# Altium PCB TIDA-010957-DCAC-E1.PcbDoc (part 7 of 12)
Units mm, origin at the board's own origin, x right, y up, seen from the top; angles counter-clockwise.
Board outline 300 x 300 mm, 4 copper layers (Top Layer, Layer 1, Layer 2, Bottom Layer), stack 1.787 mm thick; 1159 components, 619 nets, 3431 pads, 2942 vias.
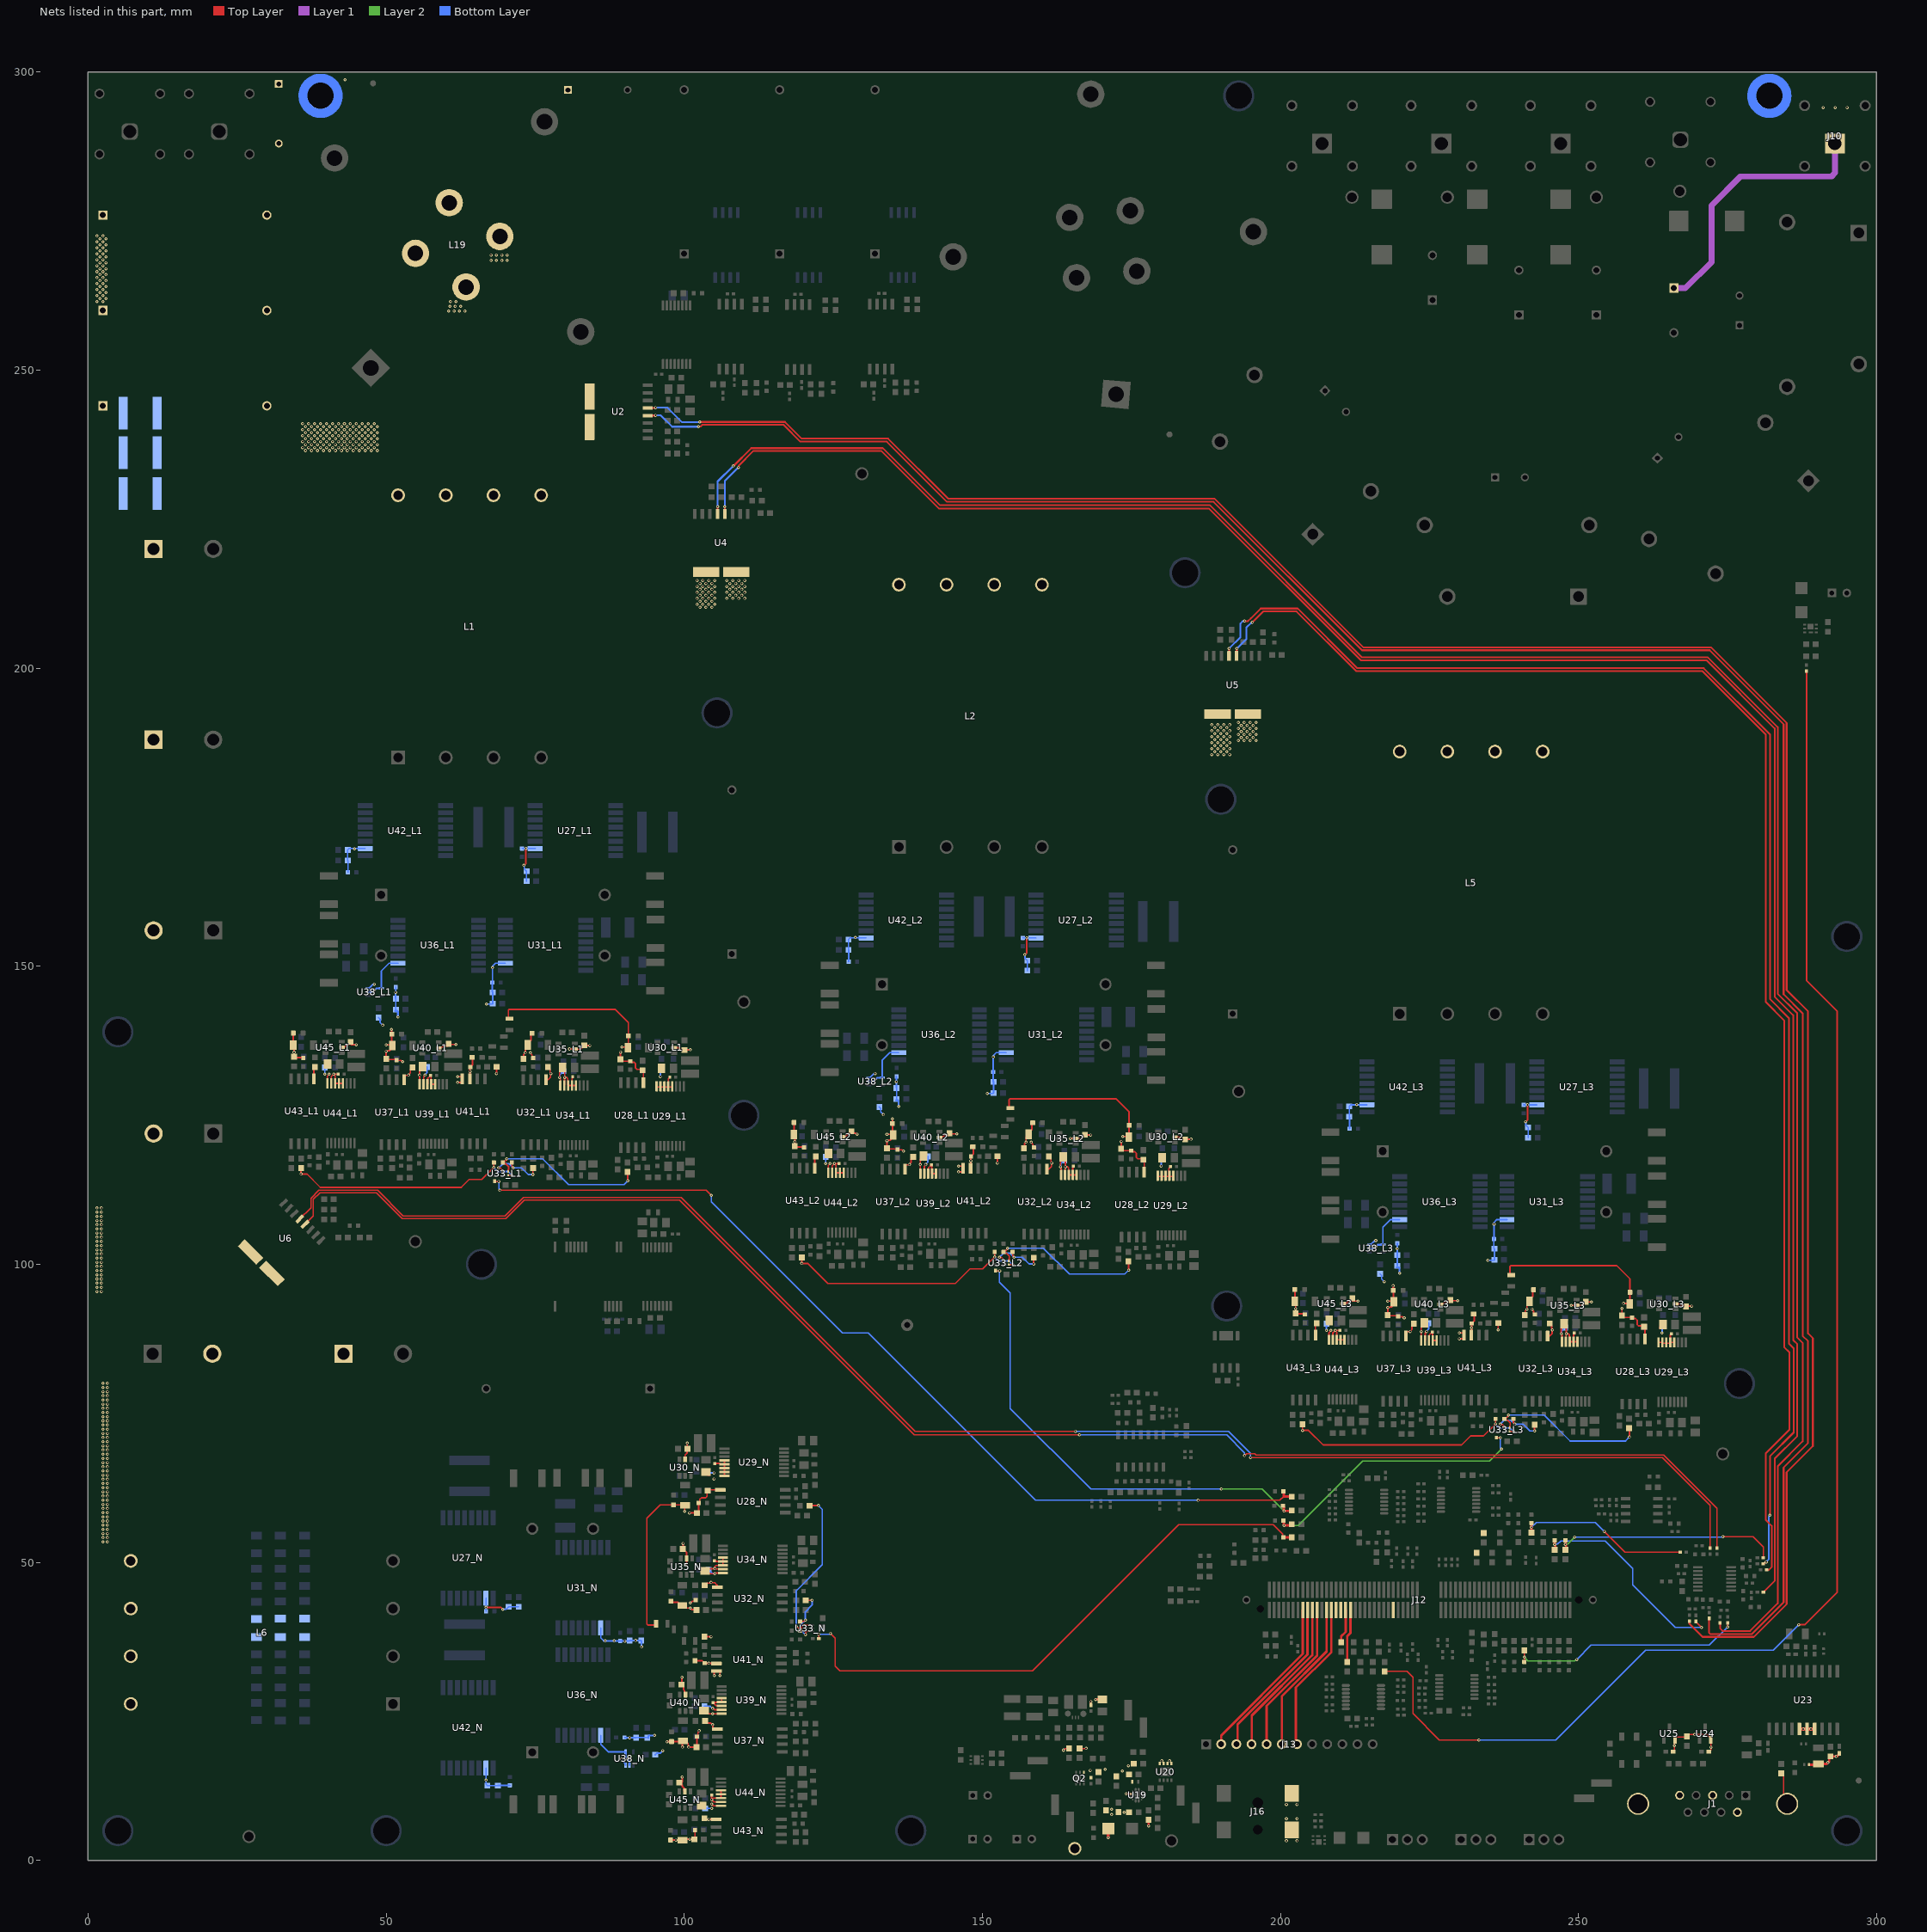
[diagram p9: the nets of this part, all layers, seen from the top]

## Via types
v1: diameter 0.508, hole 0.254, Top Layer to Bottom Layer, tented both sides, 2942 vias

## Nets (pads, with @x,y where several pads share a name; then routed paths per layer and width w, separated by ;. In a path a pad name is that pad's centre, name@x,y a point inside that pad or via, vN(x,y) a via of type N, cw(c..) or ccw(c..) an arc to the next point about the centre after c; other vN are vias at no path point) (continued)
GND_ISO_CAN: C149.2 C150.2 C151.2 C156.2 C157.1 C158.1 FB18.2 J1.3 J1.5 J1.6 J1.10 J1.11 R93.1 U23.15 U23.16 U23.17 U24.2 U25.2 | length 25.8
  Top Layer w0.2: C156.2@265.85,18.25 265.873,18.25 266.073,18.45 v1(266.073,19.262) 266.073,20.073 U25.2@266.2,20.2 266.2,20.479 266.4,20.679 268.079,20.679 C157.1@268.2,20.8 268.55,21.15 271.6,21.15 272.2,20.55 U24.2@272.2,20.2 272.2,18.5 271.95,18.25 C158.1@271.85,18.25 ; R93.1@284,14.6 284.375,14.225 284.375,10.125 J1.10@285,9.5 ; C151.2@290.1,16.05 C151.2@290.25,16.2 ; C149.2@293.75,17.85 C149.2@293.75,17.95
  Top Layer w0.4: FB18.2@288.65,16.05 C151.2@290.1,16.05 ; C151.2@290.25,16.2 291.634,16.2 292.055,16.621 292.055,17.255 C150.2@292.25,17.45 293.35,17.45 C149.2@293.75,17.85
  Top Layer w0.55: U23.15@287.06,22.05 U23.16@288.33,22.05 U23.17@289.6,22.05
  other v1: 291.845,16.411 293.229,17.45 272.2,19 269.5,21.1 287.695,22.05 288.965,22.05
GND_S1_GaN_L1: C187_L1.2 C188_L1.1 C189_L1.1 C190_L1.2 C192_L1.2 C193_L1.1 C194_L1.2 C195_L1.2 D10_L1.1 R283_L1.1 R288_L1.1 R290_L1.1 R314_L1.2 U27_L1.10 U28_L1.5 U29_L1.12 U29_L1.13 U29_L1.14 U29_L1.15 U29_L1.16 U30_L1.2 | length 52.9
  Top Layer w0.254: R314_L1.2@70.5,141.2 70.5,142.621 70.649,142.77 88.4,142.77 90.625,140.545 D10_L1.1@90.625,138.303 90.625,136.395 C192_L1.2@90.575,136.345 90.48,136.44 v1(89.55,136.44) ; v1(73.119,166.926) 73.173,166.926 73.449,167.201 v1(73.449,169.748) ; v1(89.3,135.603) C187_L1.2@89.3,134.394 89.627,134.066 C189_L1.1@90.967,134.066 91.135,133.898 91.55,133.898 91.838,133.61 91.838,132.907 92.062,132.684 92.865,132.684 C195_L1.2@93,132.548 93.155,132.393 U28_L1.5@93.155,130.45 ; U29_L1.16@95.497,129.75 96.025,129.75 96.675,129.75 97.272,129.75 U29_L1.12@97.922,129.75 ; C194_L1.2@95.664,132.196 C194_L1.2@95.664,132.569 ; U29_L1.13@97.325,129.855 97.325,131.104 C193_L1.1@97.588,131.367 ; U30_L1.2@98.288,136.345 99.013,136.345 99.322,136.036 99.322,136.014 99.973,136.014 R290_L1.1@100.047,135.94 100.096,135.989 v1(101,135.989)
  Bottom Layer w0.254: C188_L1.1@72.801,169.747 72.803,169.748 v1(73.449,169.748) 74.998,169.748 U27_L1.10@75,169.75 ; v1(73.119,166.926) 73.168,166.877 73.168,166.34 73.178,166.33 73.178,166.305 73.526,165.957 C190_L1.2@73.551,165.957 R283_L1.1@73.551,164.25
  Bottom Layer w0.3: v1(96,131.5) 96,132.7 R288_L1.1@96.2,132.9
GND_S1_GaN_L2: C187_L2.2 C188_L2.1 C189_L2.1 C190_L2.2 C192_L2.2 C193_L2.1 C194_L2.2 C195_L2.2 D10_L2.1 R283_L2.1 R288_L2.1 R290_L2.1 R314_L2.2 U27_L2.10 U28_L2.5 U29_L2.12 U29_L2.13 U29_L2.14 U29_L2.15 U29_L2.16 U30_L2.2 | length 53.1
  Top Layer w0.254: R314_L2.2@154.5,126.2 154.5,127.621 154.649,127.77 172.4,127.77 174.625,125.545 D10_L2.1@174.625,123.303 174.625,121.395 C192_L2.2@174.575,121.345 174.48,121.44 v1(173.55,121.44) ; v1(157.119,151.926) 157.173,151.926 157.449,152.201 v1(157.449,154.748) ; v1(173.3,120.603) C187_L2.2@173.3,119.394 173.627,119.066 C189_L2.1@174.967,119.066 175.135,118.898 175.55,118.898 175.838,118.61 175.838,117.907 176.062,117.684 176.865,117.684 C195_L2.2@177,117.548 177.155,117.393 U28_L2.5@177.155,115.45 ; U29_L2.16@179.497,114.75 179.972,114.75 180.622,114.75 U29_L2.13@181.272,114.75 ; C194_L2.2@179.664,117.196 C194_L2.2@179.664,117.569 ; C193_L2.1@181.588,116.367 181.272,116.051 U29_L2.13@181.272,114.75 ; U29_L2.12@181.922,114.75 U29_L2.13@181.272,114.75 ; U30_L2.2@182.288,121.345 183.013,121.345 183.322,121.036 183.322,121.014 183.973,121.014 R290_L2.1@184.047,120.94 184.096,120.989 v1(185,120.989)
  Bottom Layer w0.254: C188_L2.1@156.801,154.747 156.803,154.748 v1(157.449,154.748) 158.998,154.748 U27_L2.10@159,154.75 ; v1(157.119,151.926) 157.168,151.877 157.168,151.34 157.178,151.33 157.178,151.305 157.526,150.957 C190_L2.2@157.551,150.957 R283_L2.1@157.551,149.25
  Bottom Layer w0.3: v1(180,116.5) 180,117.7 R288_L2.1@180.2,117.9
GND_S1_GaN_L3: C187_L3.2 C188_L3.1 C189_L3.1 C190_L3.2 C192_L3.2 C193_L3.1 C194_L3.2 C195_L3.2 D10_L3.1 R283_L3.1 R288_L3.1 R290_L3.1 R314_L3.2 U27_L3.10 U28_L3.5 U29_L3.12 U29_L3.13 U29_L3.14 U29_L3.15 U29_L3.16 U30_L3.2 | length 53.1
  Top Layer w0.254: R314_L3.2@238.5,98.2 238.5,99.621 238.649,99.77 256.4,99.77 258.625,97.545 D10_L3.1@258.625,95.303 258.625,93.395 C192_L3.2@258.575,93.345 258.48,93.44 v1(257.55,93.44) ; v1(241.119,123.926) 241.173,123.926 241.449,124.201 v1(241.449,126.748) ; v1(257.3,92.603) C187_L3.2@257.3,91.394 257.627,91.066 C189_L3.1@258.967,91.066 259.135,90.898 259.55,90.898 259.838,90.61 259.838,89.907 260.062,89.684 260.865,89.684 C195_L3.2@261,89.548 261.155,89.393 U28_L3.5@261.155,87.45 ; U29_L3.16@263.425,86.9 U29_L3.15@264.075,86.9 ; C194_L3.2@263.664,89.196 C194_L3.2@263.664,89.569 ; U29_L3.15@264.147,86.75 264.725,86.75 265.272,86.75 265.297,86.75 265.4,86.853 265.4,88.179 C193_L3.1@265.588,88.367 ; U29_L3.13@265.375,86.9 U29_L3.12@266.025,86.9 ; U30_L3.2@266.288,93.345 267.013,93.345 267.322,93.036 267.322,93.014 267.973,93.014 R290_L3.1@268.047,92.94 268.096,92.989 v1(269,92.989)
  Bottom Layer w0.254: C188_L3.1@240.801,126.747 240.803,126.748 v1(241.449,126.748) 242.998,126.748 U27_L3.10@243,126.75 ; v1(241.119,123.926) 241.168,123.877 241.168,123.34 241.178,123.33 241.178,123.305 241.526,122.957 C190_L3.2@241.551,122.957 R283_L3.1@241.551,121.25
  Bottom Layer w0.3: v1(264,88.5) 264,89.7 R288_L3.1@264.2,89.9
GND_S1_GaN_N: C187_N.2 C188_N.1 C189_N.1 C190_N.2 C192_N.2 C193_N.1 C194_N.2 C195_N.2 D10_N.1 R283_N.1 R288_N.1 R290_N.1 R314_N.2 U27_N.10 U28_N.5 U29_N.12 U29_N.13 U29_N.14 U29_N.15 U29_N.16 U30_N.2 | length 53.2
  Top Layer w0.254: v1(66.752,42.449) 69.299,42.449 69.574,42.173 v1(69.574,42.119) ; R314_N.2@95.3,39.5 93.879,39.5 93.73,39.649 93.73,57.4 95.955,59.625 D10_N.1@98.197,59.625 100.105,59.625 C192_N.2@100.155,59.575 100.06,59.48 v1(100.06,58.55) ; U30_N.2@100.155,67.288 100.155,68.013 100.464,68.322 100.486,68.322 100.486,68.973 R290_N.1@100.56,69.047 100.511,69.096 v1(100.511,70) ; v1(100.897,58.3) C187_N.2@102.106,58.3 102.434,58.627 C189_N.1@102.434,59.967 102.602,60.135 102.602,60.55 102.89,60.838 103.593,60.838 103.816,61.062 103.816,61.865 C195_N.2@103.952,62 104.107,62.155 U28_N.5@106.05,62.155 ; C194_N.2@103.931,64.664 C194_N.2@104.304,64.664 ; C193_N.1@105.133,66.588 105.964,66.588 106.105,66.447 U29_N.13@106.75,66.447 ; U29_N.16@106.75,64.497 U29_N.15@106.75,65.147 U29_N.14@106.75,65.797 U29_N.13@106.75,66.447 ; U29_N.12@106.75,67.097 U29_N.13@106.75,66.447
  Bottom Layer w0.254: U27_N.10@66.75,44 66.752,43.998 v1(66.752,42.449) 66.752,41.803 C188_N.1@66.753,41.801 ; v1(69.574,42.119) 69.623,42.168 70.16,42.168 70.17,42.178 70.195,42.178 70.543,42.526 C190_N.2@70.543,42.551 R283_N.1@72.25,42.551
  Bottom Layer w0.3: R288_N.1@103.6,65.2 103.8,65 v1(105,65)
  other v1: 105,64
GND_S2_GaN_L1: C201_L1.2 C202_L1.1 C203_L1.1 C204_L1.2 C208_L1.2 C210_L1.1 C211_L1.2 C212_L1.2 D11_L1.1 R294_L1.1 R299_L1.1 R301_L1.1 U31_L1.10 U32_L1.5 U34_L1.12 U34_L1.13 U34_L1.14 U34_L1.15 U34_L1.16 U35_L1.2 | length 33.6
  Top Layer w0.254: C201_L1.2@73.005,134.466 73.07,134.531 73.07,135.199 v1(73.347,135.476) 73.347,136.393 C208_L1.2@73.755,136.8 ; v1(74.185,135.476) 74.185,135.407 74.484,135.108 74.484,134.758 C203_L1.1@74.66,134.582 ; U32_L1.5@76.815,130.95 76.853,130.988 77.174,130.988 77.581,131.396 77.581,131.95 v1(77.63,131.998) 77.63,132.067 77.503,132.194 C212_L1.2@77.503,132.723 ; U34_L1.16@79.225,130 79.225,131.155 79.1,131.28 v1(79.1,131.349) 79.1,132.239 79.584,132.723 79.95,132.357 v1(79.95,131.349) ; U34_L1.15@79.875,130 79.913,130.038 79.913,131.312 v1(79.95,131.349) ; v1(80.775,136.116) U35_L1.2@81.65,136.116 81.681,136.085 82.62,136.085 83.244,136.709 R301_L1.1@83.244,136.734 83.288,136.69 v1(84.173,136.69) ; C210_L1.1@81.394,131.367 81.175,131.148 U34_L1.13@81.175,130 ; U34_L1.12@81.825,130 U34_L1.13@81.175,130 ; v1(79.95,131.349) 80.284,131.349 80.461,131.172 80.461,130.064 U34_L1.14@80.525,130 U34_L1.13@81.175,130
  Top Layer w0.3: C208_L1.2@73.755,136.8 73.755,137.05 74.3,137.595 D11_L1.1@74.3,138.8
  Bottom Layer w0.254: v1(66.819,143.657) 67.823,143.657 R294_L1.1@67.89,143.725 67.89,145.617 C204_L1.2@67.882,145.625 67.807,145.7 C202_L1.1@67.807,147.25 67.833,147.276 67.833,150.007 68.326,150.5 U31_L1.10@70,150.5 ; v1(79.1,131.349) 79.149,131.398 79.149,131.795 79.736,132.382 R299_L1.1@79.736,132.407
  other v1: 67.833,149.758
GND_S2_GaN_L2: C201_L2.2 C202_L2.1 C203_L2.1 C204_L2.2 C208_L2.2 C210_L2.1 C211_L2.2 C212_L2.2 D11_L2.1 R294_L2.1 R299_L2.1 R301_L2.1 U31_L2.10 U32_L2.5 U34_L2.12 U34_L2.13 U34_L2.14 U34_L2.15 U34_L2.16 U35_L2.2 | length 33.6
  Top Layer w0.254: C201_L2.2@157.005,119.466 157.07,119.531 157.07,120.199 v1(157.347,120.476) 157.347,121.393 C208_L2.2@157.755,121.8 ; v1(158.185,120.476) 158.185,120.407 158.484,120.108 158.484,119.758 C203_L2.1@158.66,119.582 ; U32_L2.5@160.815,115.95 160.853,115.988 161.174,115.988 161.581,116.396 161.581,116.95 v1(161.63,116.998) 161.63,117.067 161.503,117.194 C212_L2.2@161.503,117.723 ; U34_L2.16@163.225,115 163.225,116.155 163.1,116.28 v1(163.1,116.349) 163.1,117.239 163.584,117.723 163.95,117.357 v1(163.95,116.349) ; U34_L2.15@163.875,115 163.913,115.038 163.913,116.312 v1(163.95,116.349) ; v1(164.775,121.116) U35_L2.2@165.65,121.116 165.681,121.085 166.62,121.085 167.244,121.709 R301_L2.1@167.244,121.734 167.288,121.69 v1(168.173,121.69) ; C210_L2.1@165.394,116.367 165.175,116.148 U34_L2.13@165.175,115 ; U34_L2.12@165.825,115 U34_L2.13@165.175,115 ; v1(163.95,116.349) 164.284,116.349 164.461,116.172 164.461,115.064 U34_L2.14@164.525,115 U34_L2.13@165.175,115
  Top Layer w0.3: C208_L2.2@157.755,121.8 157.755,122.05 158.3,122.595 D11_L2.1@158.3,123.8
  Bottom Layer w0.254: v1(150.819,128.657) 151.823,128.657 R294_L2.1@151.89,128.725 151.89,130.617 C204_L2.2@151.882,130.625 151.807,130.7 C202_L2.1@151.807,132.25 151.833,132.276 151.833,135.007 152.326,135.5 U31_L2.10@154,135.5 ; v1(163.1,116.349) 163.149,116.398 163.149,116.795 163.736,117.382 R299_L2.1@163.736,117.407
  other v1: 151.833,134.758
GND_S2_GaN_L3: C201_L3.2 C202_L3.1 C203_L3.1 C204_L3.2 C208_L3.2 C210_L3.1 C211_L3.2 C212_L3.2 D11_L3.1 R294_L3.1 R299_L3.1 R301_L3.1 U31_L3.10 U32_L3.5 U34_L3.12 U34_L3.13 U34_L3.14 U34_L3.15 U34_L3.16 U35_L3.2 | length 33.6
  Top Layer w0.254: C201_L3.2@241.005,91.466 241.07,91.531 241.07,92.199 v1(241.347,92.476) 241.347,93.393 C208_L3.2@241.755,93.8 ; v1(242.185,92.476) 242.185,92.407 242.484,92.108 242.484,91.758 C203_L3.1@242.66,91.582 ; U32_L3.5@244.815,87.95 244.853,87.988 245.174,87.988 245.581,88.396 245.581,88.95 v1(245.63,88.998) 245.63,89.067 245.503,89.194 C212_L3.2@245.503,89.723 ; U34_L3.16@247.225,87 247.225,88.155 247.1,88.28 v1(247.1,88.349) 247.1,89.239 247.584,89.723 247.95,89.357 v1(247.95,88.349) ; U34_L3.15@247.875,87 247.913,87.038 247.913,88.312 v1(247.95,88.349) ; v1(248.775,93.116) U35_L3.2@249.65,93.116 249.681,93.085 250.62,93.085 251.244,93.709 R301_L3.1@251.244,93.734 251.288,93.69 v1(252.173,93.69) ; C210_L3.1@249.394,88.367 249.175,88.148 U34_L3.13@249.175,87 ; U34_L3.12@249.825,87 U34_L3.13@249.175,87 ; v1(247.95,88.349) 248.284,88.349 248.461,88.172 248.461,87.064 U34_L3.14@248.525,87 U34_L3.13@249.175,87
  Top Layer w0.3: C208_L3.2@241.755,93.8 241.755,94.05 242.3,94.595 D11_L3.1@242.3,95.8
  Bottom Layer w0.254: v1(234.819,100.657) 235.823,100.657 R294_L3.1@235.89,100.725 235.89,102.617 C204_L3.2@235.882,102.625 235.807,102.7 C202_L3.1@235.807,104.25 235.833,104.276 235.833,107.007 236.326,107.5 U31_L3.10@238,107.5 ; v1(247.1,88.349) 247.149,88.398 247.149,88.795 247.736,89.382 R299_L3.1@247.736,89.407
  other v1: 235.833,106.758
GND_S2_GaN_N: C201_N.2 C202_N.1 C203_N.1 C204_N.2 C208_N.2 C210_N.1 C211_N.2 C212_N.2 D11_N.1 R294_N.1 R299_N.1 R301_N.1 U31_N.10 U32_N.5 U34_N.12 U34_N.13 U34_N.14 U34_N.15 U34_N.16 U35_N.2 | length 33.6
  Top Layer w0.254: C208_N.2@99.7,42.755 100.107,42.347 v1(101.024,42.347) 101.301,42.07 101.969,42.07 C201_N.2@102.034,42.005 ; v1(99.81,53.173) 99.81,52.288 R301_N.1@99.766,52.244 99.791,52.244 100.415,51.62 100.415,50.681 U35_N.2@100.384,50.65 v1(100.384,49.775) ; v1(101.024,43.185) 101.093,43.185 101.392,43.484 101.742,43.484 C203_N.1@101.918,43.66 ; C212_N.2@103.777,46.503 104.306,46.503 104.433,46.63 v1(104.502,46.63) 104.55,46.581 105.104,46.581 105.512,46.174 105.512,45.853 U32_N.5@105.55,45.815 ; C210_N.1@105.133,50.394 105.352,50.175 U34_N.13@106.5,50.175 ; U34_N.16@106.5,48.225 105.345,48.225 105.22,48.1 v1(105.151,48.1) 104.261,48.1 103.777,48.584 104.143,48.95 v1(105.151,48.95) ; U34_N.15@106.5,48.875 106.462,48.913 105.188,48.913 v1(105.151,48.95) ; U34_N.12@106.5,50.825 U34_N.13@106.5,50.175 ; v1(105.151,48.95) 105.151,49.284 105.328,49.461 106.436,49.461 U34_N.14@106.5,49.525 U34_N.13@106.5,50.175
  Top Layer w0.3: D11_N.1@97.7,43.3 98.905,43.3 99.45,42.755 C208_N.2@99.7,42.755
  Bottom Layer w0.254: U31_N.10@86,39 86,37.326 86.493,36.833 89.224,36.833 C202_N.1@89.25,36.807 90.8,36.807 C204_N.2@90.875,36.882 90.883,36.89 R294_N.1@92.775,36.89 92.843,36.823 v1(92.843,35.819) ; R299_N.1@104.093,48.736 104.118,48.736 104.705,48.149 105.102,48.149 v1(105.151,48.1)
  other v1: 90.025,36.807 86.742,36.833 88.242,36.833 91.829,36.89
GND_S3_GaN_L1: C225_L1.2 C226_L1.1 C227_L1.1 C228_L1.2 C229_L1.2 C232_L1.2 C233_L1.1 C234_L1.2 C235_L1.2 C241_L1.2 C242_L1.1 D12_L1.1 R304_L1.1 R309_L1.1 R311_L1.1 R315_L1.1 U36_L1.10 U37_L1.5 U38_L1.2 U38_L1.3 U38_L1.4 U39_L1.12 U39_L1.13 U39_L1.14 U39_L1.15 U39_L1.16 U40_L1.2 U41_L1.3 U41_L1.4 | length 49.4
  Top Layer w0.254: v1(50.008,136.807) C232_L1.2@50.9,136.807 ; C232_L1.2@51.029,136.508 51.029,136.258 50.606,135.835 50.356,135.835 50.315,135.794 50.056,135.794 v1(50.008,135.745) C225_L1.2@50.008,134.466 50.108,134.366 51.764,134.366 51.935,134.195 52.495,134.195 52.692,133.998 v1(52.761,133.998) ; U37_L1.5@53.034,130.95 53.034,131.526 53.207,131.699 53.733,131.699 v1(53.761,131.726) 53.761,131.795 54.056,132.09 54.056,132.675 C235_L1.2@54.404,133.023 ; U39_L1.16@55.61,130.208 v1(55.61,131.723) 55.61,132.358 ; C234_L1.2@56.142,133.182 55.634,132.674 55.634,132.382 ; U39_L1.15@56.26,130.208 56.293,130.241 56.293,131.439 56.508,131.654 v1(56.508,131.723) ; U39_L1.14@56.91,130.208 56.974,130.272 56.974,131.148 57.008,131.182 57.008,131.207 C233_L1.1@57.458,131.657 57.516,131.599 57.516,130.253 U39_L1.13@57.56,130.208 U39_L1.12@58.21,130.208 ; U40_L1.2@58.833,136.283 59.006,136.456 59.504,136.456 59.66,136.611 60.33,136.611 60.601,136.883 v1(61.725,136.883) ; v1(62,130.5) 62.591,130.5 62.764,130.673 U41_L1.4@62.764,131.108 62.764,131.303 62.591,131.476 v1(62,131.476) ; U41_L1.3@64.034,131.108 64.07,131.145 64.07,133.046 C242_L1.1@64.107,133.082 64.507,133.482 R315_L1.1@64.507,134.682 ; v1(68.525,131.998) C241_L1.2@68.525,133.116 ; 55.61,132.358 55.634,132.382 ; 55.61,132.358 55.634,132.382
  Top Layer w0.3: C232_L1.2@50.9,137 50.939,137.039 D12_L1.1@50.939,138.624 ; v1(50.9,139.4) 50.919,139.381 D12_L1.1@50.919,138.624
  Bottom Layer w0.254: C228_L1.2@48.723,141.375 48.977,141.121 48.977,140.544 v1(49.423,140.098) ; U38_L1.4@49.203,146.325 49.203,149.203 50.5,150.5 U36_L1.10@52,150.5 ; R304_L1.1@51.622,142.725 C229_L1.2@51.622,144.55 51.589,144.583 v1(51.589,145.625) 51.605,145.641 51.605,146.509 C226_L1.1@51.622,146.525 ; v1(56.508,131.723) 56.508,131.792 56.86,132.144 R309_L1.1@56.86,133.107
  Bottom Layer w0.3: U38_L1.2@46.953,145.675 47.675,145.675 v1(48,146) 48.054,146 48.329,146.275 49.153,146.275 U38_L1.4@49.203,146.325 ; U38_L1.3@46.953,146.325 47.178,146.325 47.814,146.962 47.962,146.962 v1(48,147) ; R304_L1.1@51.5,142.5 51.872,142.5 51.972,142.4 51.972,141.528 v1(52,141.5)
  other v1: 64.07,132.357
GND_S3_GaN_L2: C225_L2.2 C226_L2.1 C227_L2.1 C228_L2.2 C229_L2.2 C232_L2.2 C233_L2.1 C234_L2.2 C235_L2.2 C241_L2.2 C242_L2.1 D12_L2.1 R304_L2.1 R309_L2.1 R311_L2.1 R315_L2.1 U36_L2.10 U37_L2.5 U38_L2.2 U38_L2.3 U38_L2.4 U39_L2.12 U39_L2.13 U39_L2.14 U39_L2.15 U39_L2.16 U40_L2.2 U41_L2.3 U41_L2.4 | length 49.3
  Top Layer w0.254: v1(134.008,121.807) C232_L2.2@134.9,121.807 ; C232_L2.2@135.029,121.508 135.029,121.258 134.606,120.835 134.356,120.835 134.315,120.794 134.056,120.794 v1(134.008,120.745) C225_L2.2@134.008,119.466 134.108,119.366 135.764,119.366 135.935,119.195 136.495,119.195 136.692,118.998 v1(136.761,118.998) ; U37_L2.5@137.034,115.95 137.034,116.526 137.207,116.699 137.733,116.699 v1(137.761,116.726) 137.761,116.795 138.056,117.09 138.056,117.675 C235_L2.2@138.404,118.023 ; U39_L2.16@139.61,115.208 v1(139.61,116.723) 139.61,117.358 139.634,117.382 139.634,117.674 C234_L2.2@140.142,118.182 ; U39_L2.15@140.26,115.208 140.293,115.241 140.293,116.439 140.508,116.654 v1(140.508,116.723) ; U39_L2.14@140.91,115.208 140.974,115.272 140.974,116.148 141.008,116.182 141.008,116.207 C233_L2.1@141.458,116.657 141.516,116.599 141.516,115.253 U39_L2.13@141.56,115.208 U39_L2.12@142.21,115.208 ; U40_L2.2@142.833,121.283 143.006,121.456 143.504,121.456 143.66,121.611 144.33,121.611 144.601,121.883 v1(145.725,121.883) ; v1(146,115.5) 146.591,115.5 146.764,115.673 U41_L2.4@146.764,116.108 146.764,116.303 146.591,116.476 v1(146,116.476) ; U41_L2.3@148.034,116.108 148.07,116.145 148.07,118.046 C242_L2.1@148.107,118.082 148.507,118.482 R315_L2.1@148.507,119.682 ; v1(152.525,116.998) C241_L2.2@152.525,118.116
  Top Layer w0.3: C232_L2.2@134.9,122 134.939,122.039 D12_L2.1@134.939,123.624 ; v1(134.9,124.4) 134.919,124.381 D12_L2.1@134.919,123.624
  Bottom Layer w0.254: C228_L2.2@132.723,126.375 132.977,126.121 132.977,125.544 v1(133.423,125.098) ; U38_L2.4@133.203,131.325 133.203,134.203 134.5,135.5 U36_L2.10@136,135.5 ; R304_L2.1@135.622,127.725 C229_L2.2@135.622,129.55 135.589,129.583 v1(135.589,130.625) 135.605,130.641 135.605,131.509 C226_L2.1@135.622,131.525 ; v1(140.508,116.723) 140.508,116.792 140.86,117.144 R309_L2.1@140.86,118.107
  Bottom Layer w0.3: U38_L2.2@130.953,130.675 131.675,130.675 v1(132,131) 132.054,131 132.329,131.275 133.153,131.275 U38_L2.4@133.203,131.325 ; U38_L2.3@130.953,131.325 131.178,131.325 131.814,131.962 131.962,131.962 v1(132,132) ; R304_L2.1@135.5,127.5 135.872,127.5 135.972,127.4 135.972,126.528 v1(136,126.5)
  other v1: 148.07,117.357
GND_S3_GaN_L3: C225_L3.2 C226_L3.1 C227_L3.1 C228_L3.2 C229_L3.2 C232_L3.2 C233_L3.1 C234_L3.2 C235_L3.2 C241_L3.2 C242_L3.1 D12_L3.1 R304_L3.1 R309_L3.1 R311_L3.1 R315_L3.1 U36_L3.10 U37_L3.5 U38_L3.2 U38_L3.3 U38_L3.4 U39_L3.12 U39_L3.13 U39_L3.14 U39_L3.15 U39_L3.16 U40_L3.2 U41_L3.3 U41_L3.4 | length 49.3
  Top Layer w0.254: v1(218.008,93.807) C232_L3.2@218.9,93.807 ; C232_L3.2@219.029,93.508 219.029,93.258 218.606,92.835 218.356,92.835 218.315,92.794 218.056,92.794 v1(218.008,92.745) C225_L3.2@218.008,91.466 218.108,91.366 219.764,91.366 219.935,91.195 220.495,91.195 220.692,90.998 v1(220.761,90.998) ; U37_L3.5@221.034,87.95 221.034,88.526 221.207,88.699 221.733,88.699 v1(221.761,88.726) 221.761,88.795 222.056,89.09 222.056,89.675 C235_L3.2@222.404,90.023 ; U39_L3.16@223.61,87.208 v1(223.61,88.723) 223.61,89.358 223.634,89.382 223.634,89.674 C234_L3.2@224.142,90.182 ; U39_L3.15@224.26,87.208 224.293,87.241 224.293,88.439 224.508,88.654 v1(224.508,88.723) ; U39_L3.14@224.91,87.208 224.974,87.272 224.974,88.148 225.008,88.182 225.008,88.207 C233_L3.1@225.458,88.657 225.516,88.599 225.516,87.253 U39_L3.13@225.56,87.208 U39_L3.12@226.21,87.208 ; U40_L3.2@226.833,93.283 227.006,93.456 227.504,93.456 227.66,93.611 228.33,93.611 228.601,93.883 v1(229.725,93.883) ; v1(230,87.5) 230.591,87.5 230.764,87.673 U41_L3.4@230.764,88.108 230.764,88.303 230.591,88.476 v1(230,88.476) ; U41_L3.3@232.034,88.108 232.07,88.145 232.07,90.046 C242_L3.1@232.107,90.082 232.507,90.482 R315_L3.1@232.507,91.682 ; v1(236.525,88.998) C241_L3.2@236.525,90.116
  Top Layer w0.3: C232_L3.2@218.9,94 218.939,94.039 D12_L3.1@218.939,95.624 ; v1(218.9,96.4) 218.919,96.381 D12_L3.1@218.919,95.624
  Bottom Layer w0.254: C228_L3.2@216.723,98.375 216.977,98.121 216.977,97.544 v1(217.423,97.098) ; U38_L3.4@217.203,103.325 217.203,106.203 218.5,107.5 U36_L3.10@220,107.5 ; R304_L3.1@219.622,99.725 C229_L3.2@219.622,101.55 219.589,101.583 v1(219.589,102.625) 219.605,102.641 219.605,103.509 C226_L3.1@219.622,103.525 ; v1(224.508,88.723) 224.508,88.792 224.86,89.144 R309_L3.1@224.86,90.107
  Bottom Layer w0.3: U38_L3.2@214.953,102.675 215.675,102.675 v1(216,103) 216.054,103 216.329,103.275 217.153,103.275 U38_L3.4@217.203,103.325 ; U38_L3.3@214.953,103.325 215.178,103.325 215.814,103.962 215.962,103.962 v1(216,104) ; R304_L3.1@219.5,99.5 219.872,99.5 219.972,99.4 219.972,98.528 v1(220,98.5)
  other v1: 232.07,89.357
GND_S3_GaN_N: C225_N.2 C226_N.1 C227_N.1 C228_N.2 C229_N.2 C232_N.2 C233_N.1 C234_N.2 C235_N.2 C241_N.2 C242_N.1 D12_N.1 R304_N.1 R309_N.1 R311_N.1 R315_N.1 U36_N.10 U37_N.5 U38_N.2 U38_N.3 U38_N.4 U39_N.12 U39_N.13 U39_N.14 U39_N.15 U39_N.16 U40_N.2 U41_N.3 U41_N.4 | length 49.3
  Top Layer w0.254: v1(99.617,30.725) 99.617,29.601 99.889,29.33 99.889,28.66 100.044,28.504 100.044,28.006 U40_N.2@100.217,27.833 ; v1(99.693,19.008) C232_N.2@99.693,19.9 ; C232_N.2@99.992,20.029 100.242,20.029 100.665,19.606 100.665,19.356 100.706,19.315 100.706,19.056 v1(100.755,19.008) C225_N.2@102.034,19.008 102.134,19.108 C227_N.1@102.134,20.764 102.305,20.935 102.305,21.495 102.502,21.692 v1(102.502,21.761) ; R315_N.1@101.818,33.507 103.018,33.507 C242_N.1@103.418,33.107 103.454,33.07 105.355,33.07 U41_N.3@105.392,33.034 ; C234_N.2@103.318,25.142 103.826,24.634 104.118,24.634 104.142,24.61 v1(104.777,24.61) U39_N.16@106.292,24.61 ; C241_N.2@103.384,37.525 v1(104.502,37.525) ; C235_N.2@103.477,23.404 103.825,23.056 104.41,23.056 104.705,22.761 v1(104.774,22.761) 104.801,22.733 104.801,22.207 104.974,22.034 U37_N.5@105.55,22.034 ; v1(104.777,25.508) 104.846,25.508 105.061,25.293 106.259,25.293 U39_N.15@106.292,25.26 ; v1(105.024,31) 105.024,31.591 105.197,31.764 U41_N.4@105.392,31.764 105.827,31.764 106,31.591 v1(106,31) ; U39_N.14@106.292,25.91 106.228,25.974 105.352,25.974 105.318,26.008 105.293,26.008 C233_N.1@104.843,26.458 104.901,26.516 106.247,26.516 U39_N.13@106.292,26.56 U39_N.12@106.292,27.21
  Top Layer w0.3: v1(97.1,19.9) 97.119,19.919 D12_N.1@97.876,19.919 ; D12_N.1@97.876,19.939 99.461,19.939 C232_N.2@99.5,19.9
  Bottom Layer w0.254: U36_N.10@86,21 86,19.5 87.297,18.203 U38_N.4@90.175,18.203 ; C226_N.1@89.975,20.622 89.991,20.605 90.859,20.605 v1(90.875,20.589) 91.917,20.589 C229_N.2@91.95,20.622 R304_N.1@93.775,20.622 ; C228_N.2@95.125,17.723 95.379,17.977 95.956,17.977 v1(96.402,18.423) ; R309_N.1@103.393,25.86 104.356,25.86 104.708,25.508 v1(104.777,25.508)
  Bottom Layer w0.3: v1(89.5,17) 89.538,16.962 89.538,16.814 90.175,16.178 U38_N.3@90.175,15.953 ; U38_N.4@90.175,18.203 90.225,18.153 90.225,17.329 90.5,17.054 v1(90.5,17) 90.825,16.675 U38_N.2@90.825,15.953 ; R304_N.1@94,20.5 94,20.872 94.1,20.972 94.972,20.972 v1(95,21)
  other v1: 104.143,33.07
GND_S4_GaN_L1: C244_L1.2 C245_L1.1 C246_L1.1 C247_L1.2 C249_L1.2 C250_L1.1 C251_L1.2 C252_L1.2 D16_L1.1 R321_L1.1 R326_L1.1 R328_L1.1 U42_L1.10 U43_L1.5 U44_L1.12 U44_L1.13 U44_L1.14 U44_L1.15 U44_L1.16 U45_L1.2 | length 25.2
  Top Layer w0.254: D16_L1.1@34.425,138.584 34.425,136.768 34.561,136.633 C252_L1.2@34.561,134.798 34.677,134.682 C246_L1.1@36.111,134.682 ; U43_L1.5@37.883,131.126 37.883,132.915 C244_L1.2@38.076,133.107 ; U44_L1.16@40.154,130.338 40.154,131.569 40.451,131.866 v1(40.451,131.907) ; U44_L1.15@40.804,130.338 40.804,131.507 v1(41.203,131.907) ; C250_L1.1@41.956,131.907 v1(41.203,131.907) ; U44_L1.12@42.754,130.338 U44_L1.13@42.104,130.338 U44_L1.14@41.454,130.338 41.454,131.588 41.203,131.838 v1(41.203,131.907) ; R328_L1.1@44.044,136.908 44.117,136.834 v1(44.994,136.834)
  Top Layer w0.3: U45_L1.2@42.551,136.384 42.667,136.5 43.1,136.5 43.4,136.8 43.4,136.824 43.586,136.824 43.761,137 R328_L1.1@43.9,137
  Bottom Layer w0.254: v1(39.726,131.907) R326_L1.1@39.726,133.023 ; C245_L1.1@43.6,165.75 43.6,167.7 R321_L1.1@43.55,167.75 C247_L1.2@43.55,169.5 43.8,169.75 U42_L1.10@46.5,169.75
  other v1: 34.561,135.548 44.7,169.7
GND_S4_GaN_L2: C244_L2.2 C245_L2.1 C246_L2.1 C247_L2.2 C249_L2.2 C250_L2.1 C251_L2.2 C252_L2.2 D16_L2.1 R321_L2.1 R326_L2.1 R328_L2.1 U42_L2.10 U43_L2.5 U44_L2.12 U44_L2.13 U44_L2.14 U44_L2.15 U44_L2.16 U45_L2.2 | length 25.3
  Top Layer w0.254: D16_L2.1@118.425,123.584 118.425,121.768 118.561,121.633 C252_L2.2@118.561,119.798 118.677,119.682 C246_L2.1@120.111,119.682 ; U43_L2.5@121.883,116.126 121.883,117.915 C244_L2.2@122.076,118.107 ; U44_L2.16@124.154,115.338 124.154,116.569 124.451,116.866 v1(124.451,116.907) ; U44_L2.15@124.804,115.338 124.804,116.507 v1(125.203,116.907) ; C250_L2.1@125.956,116.907 v1(125.203,116.907) ; U44_L2.12@126.754,115.338 U44_L2.13@126.104,115.338 U44_L2.14@125.454,115.338 125.454,116.588 125.203,116.838 v1(125.203,116.907) ; R328_L2.1@128.044,122.308 128.371,121.98 128.781,121.98 128.927,121.834 v1(128.994,121.834)
  Top Layer w0.3: U45_L2.2@126.551,121.384 126.701,121.534 127.134,121.534 127.558,121.958 127.858,121.958 R328_L2.1@127.9,122
  Bottom Layer w0.254: v1(123.726,116.907) R326_L2.1@123.726,118.023 ; C245_L2.1@127.6,150.75 127.6,152.7 R321_L2.1@127.55,152.75 C247_L2.2@127.55,154.5 127.8,154.75 U42_L2.10@130.5,154.75
  other v1: 118.561,120.548 128.7,154.8
GND_S4_GaN_L3: C244_L3.2 C245_L3.1 C246_L3.1 C247_L3.2 C249_L3.2 C250_L3.1 C251_L3.2 C252_L3.2 D16_L3.1 R321_L3.1 R326_L3.1 R328_L3.1 U42_L3.10 U43_L3.5 U44_L3.12 U44_L3.13 U44_L3.14 U44_L3.15 U44_L3.16 U45_L3.2 | length 25.2
  Top Layer w0.254: D16_L3.1@202.425,95.584 202.425,93.768 202.561,93.633 C252_L3.2@202.561,91.798 202.677,91.682 C246_L3.1@204.111,91.682 ; U43_L3.5@205.883,88.126 205.883,89.915 C244_L3.2@206.076,90.107 ; U44_L3.16@208.154,87.338 208.154,88.569 208.451,88.866 v1(208.451,88.907) ; U44_L3.15@208.804,87.338 208.804,88.507 v1(209.203,88.907) ; C250_L3.1@209.956,88.907 v1(209.203,88.907) ; U44_L3.12@210.754,87.338 U44_L3.13@210.104,87.338 U44_L3.14@209.454,87.338 209.454,88.588 209.203,88.838 v1(209.203,88.907) ; R328_L3.1@212.044,93.908 212.117,93.834 v1(212.994,93.834)
  Top Layer w0.3: U45_L3.2@210.551,93.384 210.667,93.5 211.1,93.5 211.4,93.8 211.4,93.824 211.586,93.824 211.761,94 R328_L3.1@211.9,94
  Bottom Layer w0.254: v1(207.726,88.907) R326_L3.1@207.726,90.023 ; C245_L3.1@211.6,122.75 211.6,124.7 R321_L3.1@211.55,124.75 C247_L3.2@211.55,126.5 211.8,126.75 U42_L3.10@214.5,126.75
  other v1: 202.561,92.548 212.8,126.8
GND_S4_GaN_N: C244_N.2 C245_N.1 C246_N.1 C247_N.2 C249_N.2 C250_N.1 C251_N.2 C252_N.2 D16_N.1 R321_N.1 R326_N.1 R328_N.1 U42_N.10 U43_N.5 U44_N.12 U44_N.13 U44_N.14 U44_N.15 U44_N.16 U45_N.2 | length 25.2
  Top Layer w0.254: D16_N.1@97.916,3.425 99.732,3.425 99.867,3.561 C252_N.2@101.702,3.561 101.818,3.677 C246_N.1@101.818,5.111 ; R328_N.1@99.592,13.044 99.666,13.117 v1(99.666,13.994) ; C244_N.2@103.393,7.076 103.585,6.883 U43_N.5@105.374,6.883 ; v1(104.593,9.451) 104.634,9.451 104.931,9.154 U44_N.16@106.162,9.154 ; C250_N.1@104.593,10.956 v1(104.593,10.203) ; U44_N.15@106.162,9.804 104.993,9.804 v1(104.593,10.203) ; U44_N.12@106.162,11.754 U44_N.13@106.162,11.104 U44_N.14@106.162,10.454 104.912,10.454 104.662,10.203 v1(104.593,10.203)
  Top Layer w0.3: R328_N.1@99.5,12.9 99.5,12.761 99.676,12.586 99.676,12.4 99.7,12.4 100,12.1 100,11.667 U45_N.2@100.116,11.551
  Bottom Layer w0.254: U42_N.10@66.75,15.5 66.75,12.8 C247_N.2@67,12.55 R321_N.1@68.75,12.55 68.8,12.6 C245_N.1@70.75,12.6 ; R326_N.1@103.477,8.726 v1(104.593,8.726)
  other v1: 98.603,3.425 100.952,3.561 104.143,6.883 66.75,13.462
GNDP: C131.2 C132.2 C133.2 C134.2 C135.2 C136.2 C141.2 C142.1 C146.2 D5.2 J16.2 J16.3 Q2.4 Q2.7 R206.1 R207.1 R211.1 R212.1 R216.2 TP6.1 U19.8 U20.5 U20.6 U20.7 U20.8 | length 7.3
  Top Layer w0.2: v1(163.6,18.5) 163.871,18.771 R216.2@164.538,18.771 ; C146.2@166.32,18.771 167.371,18.771 v1(167.4,18.8) ; C141.2@170.126,27.003 C141.2@170.133,27.01 ; D5.2@171.119,5.34 D5.2@171.126,5.334
  Top Layer w0.25: v1(174.109,11.188) 174.146,11.15 U19.8@175.079,11.15
  Top Layer w0.4: C142.1@168.207,26.044 v1@168.207,26.637 ; v1(169.027,27.003) C141.2@170.126,27.003 ; v1(177.9,5.8) R211.1@177.9,6.8
  Top Layer w0.5: v1(171.126,3.854) D5.2@171.126,5.334
  other v1: 201,3.3 202.8,3.3 201,7 202.8,7 171.7,7.7 173.769,8.075 171.7,8.6 201,9.4 202.8,9.4 173.5,15 168.1,15.1 170.6,15.3 174.5,15.9 180.1,16.7 181.4,16.7 168.207,26.638
GPIO1: J12.86 R86.2 | length 8.9
  Top Layer w0.4: R86.2@211.2,33.3 211.2,37.6 211.75,38.15 J12.86@211.75,42
GPIO2: J12.88 R88.2 | length 5.7
  Top Layer w0.4: R88.2@210.2,36.6 210.2,37.6 210.95,38.35 J12.88@210.95,42
GPIO3: J12.90
GPIO4: J12.92
GPIOA: J12.94 J13.7 | length 24.9
  Top Layer w0.4: J13.7@202.7,19.6 202.6,19.7 202.6,29 208.55,34.95 J12.94@208.55,42
GPIOB: J12.96 J13.6 | length 25.6
  Top Layer w0.4: J13.6@200.23,19.53 200.23,27.53 207.75,35.05 J12.96@207.75,42
GPIOC: J12.100 J13.5 | length 26
  Top Layer w0.4: J13.5@197.7,19.5 197.7,25.9 206.15,34.35 J12.100@206.15,42
GPIOD: J12.102 J13.4 | length 26.7
  Top Layer w0.4: J13.4@195.2,19.5 195.2,24.3 205.35,34.45 J12.102@205.35,42
GPIOE: J12.104 J13.3 | length 27.4
  Top Layer w0.4: J13.3@192.61,19.5 192.813,19.703 192.813,22.813 204.55,34.55 J12.104@204.55,42
GPIOF: J12.106 J13.2 | length 28.2
  Top Layer w0.4: J13.2@190.07,19.5 190.07,20.97 203.75,34.65 J12.106@203.75,42
GPIOG: J12.68
GRID_GND: J10.1 MP6.1 R94.1 | length 45.5
  Layer 1 w1: R94.1@266,263.75 267.95,263.75 272.3,268.1 272.3,277.6 277.174,282.474 292.414,282.474 293,283.059 J10.1@293,288
  other v1: 291.04,294.036 293.04,294.036 295.04,294.036
GRID_GND_1: C24.1 C25.1 MP4.1
  other v1: 43.1,298.7
GRID_RELAYS: R63.1 R96.1 | length 251
  Top Layer w0.2: R63.1@217.5,31.7 221.2,31.7 222.205,30.695 222.205,24.64 226.645,20.2 v1(233.3,20.2)
  Top Layer w0.3: v1(286.92,39.538) 287.938,39.538 293.4,45 293.4,142.45 288.25,147.6 R96.1@288.25,199.4
  Bottom Layer w0.2: v1(233.3,20.2) 246.155,20.2 261.255,35.3 282.682,35.3 v1(286.92,39.538)
I_L1_VREF: R102.2 U2.7 | length 384.4
  Top Layer w0.3: U2.7@93.875,243.635 93.907,243.667 95.267,243.667 v1@95.3,243.7 ; v1(102.6,241.3) 116.9,241.3 119.7,238.5 134.2,238.5 144.247,228.453 188.947,228.453 213.9,203.5 272.2,203.5 284.9,190.8 284.9,146 288.5,142.4 288.5,88.4 289.3,87.6 289.3,69.5 284.9,65.1 284.9,43 279.4,37.5 270.8,37.5 268.6,39.7 R102.2@268.6,40.095
  Bottom Layer w0.3: v1(95.2,243.7) 97.2,243.7 99.655,241.245 102.545,241.245 v1(102.6,241.3)
I_L2_VREF: R110.2 U4.7 | length 368
  Top Layer w0.3: U4.7@105.5,226 105.587,226.087 105.587,227.087 v1(105.6,227.1) ; v1@108.263,233.91 111.253,236.9 133.3,236.9 142.886,227.314 188.186,227.314 213.7,201.8 271.7,201.8 283.4,190.1 283.4,145.4 286.7,142.1 286.7,87.7 287.6,86.8 287.6,70.3 283.4,66.1 283.4,43.1 278.8,38.5 274.176,38.5 273.75,38.926 R110.2@273.75,39.863
  Bottom Layer w0.3: v1(105.6,227.1) 105.6,231.3 108.21,233.91 v1(108.24,233.91)
I_L3_VREF: R118.2 U5.7 | length 247.7
  Top Layer w0.2: R118.2@280.993,49.75 R118.2@281.043,49.75 ; v1@281.375,50.082 v1(281.481,50.082)
  Top Layer w0.3: U5.7@191.4,202.2 191.383,202.218 191.383,203.282 v1(191.4,203.3) ; v1(194,207.9) 194.574,207.9 195.029,208.355 195.055,208.355 196.7,210 202.9,210 212.9,200 271,200 282.1,188.9 282.1,144.5 285.3,141.3 285.3,86.7 286.1,85.9 286.1,71.8 282.1,67.8 v1(282.1,57.9) ; R118.2@281.043,49.75 v1@281.375,50.082
  Bottom Layer w0.3: v1(191.4,203.3) 193.3,205.2 193.3,207.5 193.7,207.9 v1(194,207.9) ; v1(281.481,50.082) 281.9,50.5 281.9,57.616 282.1,57.816 v1(282.1,57.9)
I_N_VREF: R126.2 U6.7 | length 271.6
  Top Layer w0.2: U6.7@35.498,107.603 37.4,109.504 37.4,111.066 38.734,112.4 48.566,112.4 52.866,108.1 69.934,108.1 73.034,111.2 99.5,111.2 138.7,72 v1(165.6,72) ; v1(195,67.6) 264.1,67.6 272.1,59.6 R126.2@272.1,52.4
  Bottom Layer w0.2: v1(165.6,72) 165.605,72.005 191.295,72.005 195,68.3 v1(195,67.6)
I_PCC_L1+: C17.2 L19.2 U2.1
  other v1: 60.5,259.9 61.4,259.9 62.3,259.9 63.2,259.9 60.7,260.7 61.6,260.7 62.5,260.7 60.8,261.5 61.7,261.5
I_PCC_L1-: L1.5 L1.6 L1.7 L1.8 U2.2
I_PCC_L2+: C18.2 L19.4 U4.1
  other v1: 102.64,210.21 103.64,210.21 104.64,210.21 102.14,210.71 103.14,210.71 104.14,210.71 105.14,210.71 102.64,211.21 103.64,211.21 104.64,211.21 102.14,211.71 103.14,211.71 104.14,211.71 105.14,211.71 102.64,212.21 103.64,212.21 104.64,212.21 102.14,212.71 103.14,212.71 104.14,212.71 105.14,212.71 102.64,213.21 103.64,213.21 104.64,213.21 102.14,213.71 103.14,213.71 104.14,213.71 105.14,213.71 102.64,214.21 103.64,214.21 104.64,214.21 102.14,214.71 103.14,214.71 104.14,214.71 105.14,214.71 67.6,268.4 68.5,268.4 69.4,268.4 70.3,268.4 67.6,269.3 68.5,269.3 69.4,269.3 70.3,269.3
I_PCC_L2-: L2.5 L2.6 L2.7 L2.8 U4.2
  other v1: 107.14,211.71 108.14,211.71 109.14,211.71 110.14,211.71 107.64,212.21 108.64,212.21 109.64,212.21 107.14,212.71 108.14,212.71 109.14,212.71 110.14,212.71 107.64,213.21 108.64,213.21 109.64,213.21 107.14,213.71 108.14,213.71 109.14,213.71 110.14,213.71 107.64,214.21 108.64,214.21 109.64,214.21 107.14,214.71 108.14,214.71 109.14,214.71 110.14,214.71
I_PCC_L3+: C19.2 L19.6 U5.1
  other v1: 188.5,185.5 189.5,185.5 190.5,185.5 191.5,185.5 189,186 190,186 191,186 188.5,186.5 189.5,186.5 190.5,186.5 191.5,186.5 189,187 190,187 191,187 188.5,187.5 189.5,187.5 190.5,187.5 191.5,187.5 189,188 190,188 191,188 188.5,188.5 189.5,188.5 190.5,188.5 191.5,188.5 189,189 190,189 191,189 188.5,189.5 189.5,189.5 190.5,189.5 191.5,189.5 189,190 190,190 191,190 188.5,190.5 189.5,190.5 190.5,190.5 191.5,190.5 36.5,236.5 37.5,236.5 38.5,236.5 39.5,236.5 40.5,236.5 41.5,236.5 42.5,236.5 43.5,236.5 44.5,236.5 45.5,236.5 46.5,236.5 47.5,236.5 48.5,236.5 36,237 37,237 38,237 39,237 40,237 41,237 42,237 43,237 44,237 45,237 46,237 47,237 48,237 36.5,237.5 37.5,237.5 38.5,237.5 39.5,237.5 40.5,237.5 41.5,237.5 42.5,237.5 43.5,237.5 44.5,237.5 45.5,237.5 46.5,237.5 47.5,237.5 48.5,237.5 36,238 37,238 38,238 39,238 40,238 41,238 42,238 43,238 44,238 45,238 46,238 47,238 48,238 36.5,238.5 37.5,238.5 38.5,238.5 39.5,238.5 40.5,238.5 41.5,238.5 42.5,238.5 43.5,238.5 44.5,238.5 45.5,238.5 46.5,238.5 47.5,238.5 48.5,238.5 36,239 37,239 38,239 39,239 40,239 41,239 42,239 43,239 44,239 45,239 46,239 47,239 48,239 36.5,239.5 37.5,239.5 38.5,239.5 39.5,239.5 40.5,239.5 41.5,239.5 42.5,239.5 43.5,239.5 44.5,239.5 45.5,239.5 46.5,239.5 47.5,239.5 48.5,239.5 36,240 37,240 38,240 39,240 40,240 41,240 42,240 43,240 44,240 45,240 46,240 47,240 48,240 36.5,240.5 37.5,240.5 38.5,240.5 39.5,240.5 40.5,240.5 41.5,240.5 42.5,240.5 43.5,240.5 44.5,240.5 45.5,240.5 46.5,240.5 47.5,240.5 48.5,240.5 36,241 37,241 38,241 39,241 40,241 41,241 42,241 43,241 44,241 45,241 46,241 47,241 48,241
I_PCC_L3-: L5.5 L5.6 L5.7 L5.8 U5.2
  other v1: 192.931,187.875 193.931,187.875 194.931,187.875 195.931,187.875 193.431,188.375 194.431,188.375 195.431,188.375 192.931,188.875 193.931,188.875 194.931,188.875 195.931,188.875 193.431,189.375 194.431,189.375 195.431,189.375 192.931,189.875 193.931,189.875 194.931,189.875 195.931,189.875 193.431,190.375 194.431,190.375 195.431,190.375 192.931,190.875 193.931,190.875 194.931,190.875 195.931,190.875
I_PCC_N+: C17.1 C18.1 C19.1 C23.1 C24.2 C257.1 C258.1 L19.8 U6.1
  other v1: 1.5,95.437 2.25,95.437 1.5,96.137 2.25,96.137 1.5,96.837 2.25,96.837 1.5,97.537 2.25,97.537 1.5,98.237 2.25,98.237 1.5,98.937 2.25,98.937 1.5,99.637 2.25,99.637 1.5,100.337 2.25,100.337 1.5,101.037 2.25,101.037 1.5,101.738 2.25,101.738 1.5,102.438 2.25,102.438 1.5,103.138 2.25,103.138 1.5,103.838 2.25,103.838 1.5,104.538 2.25,104.538 1.5,105.238 2.25,105.238 1.5,105.938 2.25,105.938 1.5,106.638 2.25,106.638 1.5,107.338 2.25,107.338 1.5,108.038 2.25,108.038 1.5,108.738 2.25,108.738 1.5,109.438 2.25,109.438 1.5,261.5 2.5,261.5 2.5,261.5 2,262 3,262 1.5,262.5 2.5,262.5 2,263 3,263 1.5,263.5 2.5,263.5 2,264 3,264 1.5,264.5 2.5,264.5 2,265 3,265 1.5,265.5 2.5,265.5 2,266 3,266 1.5,266.5 2.5,266.5 2,267 3,267 1.5,267.5 2.5,267.5 2,268 3,268 1.5,268.5 2.5,268.5 2,269 3,269 1.5,269.5 2.5,269.5 2,270 3,270 1.5,270.5 2.5,270.5 2,271 3,271 1.5,271.5 2.5,271.5 2,272 3,272 1.5,272.5 2.5,272.5
I_PCC_N-: L6.5 L6.6 L6.7 L6.8 U6.2
  other v1: 2.5,53.437 3.25,53.437 2.5,54.137 3.25,54.137 2.5,54.837 3.25,54.837 2.5,55.537 3.25,55.537 2.5,56.237 3.25,56.237 2.5,56.937 3.25,56.937 2.5,57.637 3.25,57.637 2.5,58.337 3.25,58.337 2.5,59.037 3.25,59.037 2.5,59.738 3.25,59.738 2.5,60.438 3.25,60.438 2.5,61.138 3.25,61.138 2.5,61.838 3.25,61.838 2.5,62.538 3.25,62.538 2.5,63.238 3.25,63.238 2.5,63.938 3.25,63.938 2.5,64.638 3.25,64.638 2.5,65.338 3.25,65.338 2.5,66.038 3.25,66.038 2.5,66.738 3.25,66.738 2.5,67.438 3.25,67.438 2.5,68.137 3.25,68.137 2.5,68.837 3.25,68.837 2.5,69.537 3.25,69.537 2.5,70.237 3.25,70.237 2.5,70.937 3.25,70.937 2.5,71.637 3.25,71.637 2.5,72.337 3.25,72.337 2.5,73.037 3.25,73.037 2.5,73.738 3.25,73.738 2.5,74.438 3.25,74.438 2.5,75.138 3.25,75.138 2.5,75.838 3.25,75.838 2.5,76.538 3.25,76.538 2.5,77.238 3.25,77.238 2.5,77.938 3.25,77.938 2.5,78.638 3.25,78.638 2.5,79.338 3.25,79.338 2.5,80.038 3.25,80.038
I_SENSE_1: R39.2
I_SENSE_2: R40.2
I_SENSE_PCC_L1: C31.2 R21.2 R101.2 | length 35.5
  Top Layer w0.2: R101.2@269.7,40.1 269.85,39.95 269.85,39.85 v1(270.6,39.1)
  Top Layer w0.4: R21.2@246,52.1 246.1,52.2 v1@246.1,53 ; v1@246,53 v1(246,53.005) C31.2@246,53.7
  Bottom Layer w0.2: v1(246,53.005) 246.039,53.044 246.444,53.044 247.01,53.61 254.49,53.61 259.1,49 259.1,46.2 266.2,39.1 v1(270.6,39.1)
I_SENSE_PCC_L2: C37.2 R32.1 R108.2 | length 39.3
  Top Layer w0.2: C37.2@240.9,33.3 v1(240.9,34.1) R32.1@240.9,35.2 ; v1(275,39.155) 275.025,39.18 275.025,39.838 R108.2@275.05,39.863
  Layer 2 w0.2: v1(240.9,34.1) 241.505,33.495 249.384,33.495 249.589,33.7 v1(249.7,33.7)
  Bottom Layer w0.2: v1(249.7,33.7) 252.1,36.1 271.945,36.1 v1(275,39.155)
I_SENSE_PCC_L3: C43.2 R20.2 R116.2 | length 37.7
  Top Layer w0.2: v1(274.2,54.3) 279.3,54.3 280.993,52.607 R116.2@280.993,50.8
  Top Layer w0.4: R20.2@247.8,52.1 247.9,52.2 v1@247.9,53 ; v1(247.8,53.005) 247.84,53.045 C43.2@247.84,53.54
  Layer 2 w0.2: v1(247.8,53.005) 247.878,53.083 248.183,53.083 v1(249.35,54.25)
  Bottom Layer w0.2: v1(249.35,54.25) 274.15,54.25 v1(274.2,54.3)
I_SENSE_PCC_N: C50.2 R26.2 R125.2 | length 28.9
  Top Layer w0.2: v1(254.3,55.2) 257.816,51.684 R125.2@267.05,51.684
  Top Layer w0.4: R26.2@242.1,55 v1(242.1,55.9) C50.2@242.1,56.5
  Bottom Layer w0.2: v1(242.1,55.9) 242.9,56.7 252.8,56.7 v1(254.3,55.2)
I_VOUT_L1: R100.2 U2.6 | length 380
  Top Layer w0.3: U2.6@93.875,242.365 93.892,242.382 95.182,242.382 v1(95.2,242.4) ; v1(102.4,240.5) 102.459,240.559 102.785,240.559 103.026,240.8 116.693,240.8 119.493,238 133.993,238 144.087,227.906 188.787,227.906 213.693,203 271.993,203 284.4,190.593 284.4,145.3 287.6,142.1 287.6,88 288.5,87.1 288.5,70 284.4,65.9 284.4,43.3 279.1,38 272.076,38 271.9,38.176 R100.2@271.9,40.6
  Bottom Layer w0.3: v1(95.2,242.4) 96.074,242.4 97.974,240.5 v1@102.3,240.5
I_VOUT_L2: R107.2 U4.6 | length 352.1
  Top Layer w0.3: U4.6@106.7,225.8 106.822,225.922 106.822,227.078 v1(106.8,227.1) ; v1(109.097,233.684) 109.136,233.724 109.136,233.983 111.553,236.4 133.093,236.4 138.3,231.193 142.748,226.744 188.048,226.744 213.493,201.3 271.493,201.3 282.9,189.893 282.9,144.9 286,141.8 286,87.3 286.7,86.6 286.7,71.2 282.9,67.4 282.9,46.9 281.15,45.15 281.15,45.1 281.05,45 R107.2@281,45
  Bottom Layer w0.3: v1(106.8,227.1) 106.8,231.388 v1(109.097,233.684)
I_VOUT_L3: R115.2 U5.6 | length 246.5
  Top Layer w0.3: U5.6@192.6,202.1 192.667,202.167 192.667,203.267 v1(192.7,203.3) ; v1(195.3,207.7) 197.1,209.5 202.693,209.5 212.693,199.5 270.793,199.5 281.4,188.893 281.4,144 284.5,140.9 284.5,86.1 285.4,85.2 285.4,72.3 281.4,68.3 281.4,57.121 282.4,56.121 282.4,49.2 281.932,48.732 R115.2@281.567,48.732
  Bottom Layer w0.3: v1(192.7,203.3) 194.3,204.9 194.3,206.8 195.1,207.6 v1@195.2,207.6
I_VOUT_N: R124.2 U6.6 | length 272.3
  Top Layer w0.2: U6.6@36.396,106.705 37.8,108.108 37.8,110.9 38.9,112 48.4,112 52.7,107.7 70.1,107.7 73.2,110.8 99.2,110.8 138.6,71.4 165.345,71.4 165.349,71.395 166.295,71.395 v1(166.3,71.4) ; v1(194,67.9) 194.017,67.9 194.322,68.205 195.695,68.205 195.9,68 264.266,68 273.2,59.066 R124.2@273.2,52.4
  Bottom Layer w0.2: v1(166.3,71.4) 191,71.4 194,68.4 v1(194,67.9)
Middle_Point: C1.1 C2.1 C3.1 C7.2 C8.2 C9.2 C23.2 C257.2 C258.2 R7.1 R8.1 R9.1 R10.2 R11.2 R12.2 | length 0.9
  Bottom Layer w0.5: C9.2@11,121.936 C9.2@11.436,121.936 ; C7.2@20.5,85 C7.2@20.846,84.654
MONITOR_GaN_ISO_L1: C159.2 R68.2 R293_L1.1 | length 158.4
  Top Layer w0.2: R293_L1.1@68.2,113.934 68.234,113.9 v1(68.9,113.9) ; v1(69.1,112.4) 103.7,112.4 v1(104.55,111.55) ; v1(186.2,60.4) 199.9,60.4 200.6,61.1
  Top Layer w0.4: C159.2@200.5,62 200.56,61.94 200.56,61.14 200.6,61.1 200.64,61.06 201.76,61.06 R68.2@201.8,61.1
  Bottom Layer w0.2: v1(68.9,113.9) 68.9,112.711 69.1,112.511 v1(69.1,112.4) ; v1(104.55,111.55) 104.55,110.45 126.55,88.45 130.85,88.45 158.9,60.4 v1(186.2,60.4)
MONITOR_GaN_ISO_L2: C160.2 R70.2 R293_L2.1 | length 79.6
  Top Layer w0.2: R293_L2.1@152.2,98.934 152.234,98.9 v1(152.9,98.9)
  Top Layer w0.4: C160.2@200.4,59.5 200.55,59.35 v1@200.55,58.707 ; v1(200.6,58.6) 200.64,58.64 201.66,58.64 R70.2@201.7,58.6
  Layer 2 w0.2: v1(190.1,62.3) 196.9,62.3 v1(200.6,58.6)
  Bottom Layer w0.2: v1(152.9,98.9) 152.9,96.993 154.7,95.193 154.7,75.8 168.2,62.3 v1(190.1,62.3)
MONITOR_GaN_ISO_L3: C161.2 R72.2 R293_L3.1 | length 46.8
  Top Layer w0.2: R293_L3.1@236.2,70.934 236.234,70.9 v1(236.9,70.9)
  Top Layer w0.4: C161.2@200.6,57.1 200.56,57.06 200.56,56.24 v1(200.6,56.2) 201.7,56.2 R72.2@201.9,56.4
  Layer 2 w0.2: v1(200.6,56.2) 203,56.2 213.8,67 235.1,67 v1(237.1,69)
  Bottom Layer w0.2: v1(236.9,70.9) 236.9,69.2 v1(237.1,69)
MONITOR_GaN_ISO_N: C162.2 R73.2 R293_N.1 | length 96.7
  Top Layer w0.2: R293_N.1@122.566,37.2 122.6,37.234 v1(122.6,37.9) ; v1(124.5,38.1) 125.337,37.263 125.337,32.58 126.117,31.8 158.405,31.8 182.905,56.3 198.8,56.3 200.367,54.733 200.367,54.333 C162.2@200.5,54.2
  Top Layer w0.4: C162.2@200.5,54.2 R73.2@201.9,54.2
  Bottom Layer w0.2: v1(122.6,37.9) 124.3,37.9 v1(124.5,38.1)
MONITOR_S1_GaN_ISO_L1: C209_L1.2 R278_L1.1 U33_L1.1 | length 27
  Top Layer w0.254: v1(70.24,117.699) 70.192,117.651 70.192,117.512 69.966,117.286 69.789,117.286 C209_L1.2@69.566,117.063 69.777,116.852 70.105,116.852 70.537,116.421 70.537,115.939 70.472,115.874 70.472,115.558 U33_L1.1@70.456,115.542 ; R278_L1.1@90.48,115.492 90.537,115.435 v1(90.537,114.007)
  Bottom Layer w0.254: v1(70.24,117.699) 76.248,117.699 80.594,113.353 89.883,113.353 v1(90.537,114.007)
MONITOR_S1_GaN_ISO_L2: C209_L2.2 R278_L2.1 U33_L2.1 | length 27
  Top Layer w0.254: v1(154.24,102.699) 154.192,102.651 154.192,102.512 153.966,102.286 153.789,102.286 C209_L2.2@153.566,102.063 153.777,101.852 154.105,101.852 154.537,101.421 154.537,100.939 154.472,100.874 154.472,100.558 U33_L2.1@154.456,100.542 ; R278_L2.1@174.48,100.492 174.537,100.435 v1(174.537,99.007)
  Bottom Layer w0.254: v1(154.24,102.699) 160.248,102.699 164.594,98.353 173.883,98.353 v1(174.537,99.007)
MONITOR_S1_GaN_ISO_L3: C209_L3.2 R278_L3.1 U33_L3.1 | length 27
  Top Layer w0.254: v1(238.24,74.699) 238.192,74.651 238.192,74.512 237.966,74.286 237.789,74.286 C209_L3.2@237.566,74.063 237.777,73.852 238.105,73.852 238.537,73.421 238.537,72.939 238.472,72.874 238.472,72.558 U33_L3.1@238.456,72.542 ; R278_L3.1@258.48,72.492 258.537,72.435 v1(258.537,71.007)
  Bottom Layer w0.254: v1(238.24,74.699) 244.248,74.699 248.594,70.353 257.883,70.353 v1(258.537,71.007)
MONITOR_S1_GaN_ISO_N: C209_N.2 R278_N.1 U33_N.1 | length 27
  Top Layer w0.254: v1(118.801,39.24) 118.849,39.192 118.988,39.192 119.214,38.966 119.214,38.789 C209_N.2@119.437,38.566 119.648,38.777 119.648,39.105 120.079,39.537 120.561,39.537 120.626,39.472 120.942,39.472 U33_N.1@120.958,39.456 ; R278_N.1@121.008,59.48 121.065,59.537 v1(122.493,59.537)
  Bottom Layer w0.254: v1(118.801,39.24) 118.801,45.248 123.147,49.594 123.147,58.883 v1(122.493,59.537)
MONITOR_S2_GaN_ISO_L1: C207_L1.2 R291_L1.1 U33_L1.3 | length 9.8
  Top Layer w0.254: v1(68.881,116.18) 68.93,116.131 69.226,116.131 69.433,115.925 U33_L1.3@69.433,115.702 ; U33_L1.3@69.433,115.702 69.433,115.64 69.456,115.617 U33_L1.3@69.456,115.567 ; C207_L1.2@71.084,117.063 71.084,116.446 71.306,116.224 v1(71.306,116.18) ; v1(74.616,115.058) 74.616,116.066 R291_L1.1@74.66,116.111
  Bottom Layer w0.254: v1(68.881,116.18) 69.554,116.852 70.634,116.852 v1(71.306,116.18) 72.705,116.18 73.827,115.058 v1(74.616,115.058)
MONITOR_S2_GaN_ISO_L2: C207_L2.2 R291_L2.1 U33_L2.3 | length 9.8
  Top Layer w0.254: v1(152.881,101.18) 152.93,101.131 153.226,101.131 153.433,100.925 U33_L2.3@153.433,100.702 ; U33_L2.3@153.433,100.702 153.433,100.64 153.456,100.617 U33_L2.3@153.456,100.567 ; C207_L2.2@155.084,102.063 155.084,101.446 155.306,101.224 v1(155.306,101.18) ; v1(158.616,100.058) 158.616,101.066 R291_L2.1@158.66,101.111
  Bottom Layer w0.254: v1(152.881,101.18) 153.554,101.852 154.634,101.852 v1(155.306,101.18) 156.705,101.18 157.827,100.058 v1(158.616,100.058)
MONITOR_S2_GaN_ISO_L3: C207_L3.2 R291_L3.1 U33_L3.3 | length 9.8
  Top Layer w0.254: v1(236.881,73.18) 236.93,73.131 237.226,73.131 237.433,72.925 U33_L3.3@237.433,72.702 ; U33_L3.3@237.433,72.702 237.433,72.64 237.456,72.617 U33_L3.3@237.456,72.567 ; C207_L3.2@239.084,74.063 239.084,73.446 239.306,73.224 v1(239.306,73.18) ; v1(242.616,72.058) 242.616,73.066 R291_L3.1@242.66,73.111
  Bottom Layer w0.254: v1(236.881,73.18) 237.554,73.852 238.634,73.852 v1(239.306,73.18) 240.705,73.18 241.827,72.058 v1(242.616,72.058)
MONITOR_S2_GaN_ISO_N: C207_N.2 R291_N.1 U33_N.3 | length 9.8
  Top Layer w0.254: C207_N.2@119.437,40.084 120.054,40.084 120.276,40.306 v1(120.32,40.306) ; v1(120.32,37.881) 120.369,37.93 120.369,38.226 120.575,38.433 U33_N.3@120.798,38.433 ; R291_N.1@120.389,43.66 120.434,43.616 v1(121.442,43.616) ; U33_N.3@120.798,38.433 120.86,38.433 120.883,38.456 U33_N.3@120.933,38.456
  Bottom Layer w0.254: v1(120.32,37.881) 119.648,38.554 119.648,39.634 v1(120.32,40.306) 120.32,41.705 121.442,42.827 v1(121.442,43.616)
MONITOR_S4_GaN_ISO_L1: C206_L1.2 R316_L1.1 U33_L1.6 | length 40.7
  Top Layer w0.254: R316_L1.1@35.725,116.155 35.718,116.147 v1(35.718,115.142) 36.726,115.142 38.968,112.9 62.6,112.9 63.917,114.217 66.068,114.217 v1(68.075,116.224) C206_L1.2@68.075,117.063 ; U33_L1.6@70.456,114.967 v1(71.084,114.967)
  Bottom Layer w0.254: v1(68.075,116.224) 68.075,116.165 68.676,115.564 70.488,115.564 v1(71.084,114.967)
MONITOR_S4_GaN_ISO_L2: C206_L2.2 R316_L2.1 U33_L2.6 | length 41.6
  Top Layer w0.254: R316_L2.1@119.725,101.155 119.718,101.147 v1(119.718,100.142) 120.726,100.142 124.089,96.779 145.479,96.779 147.917,99.217 150.068,99.217 v1(152.075,101.224) C206_L2.2@152.075,102.063 ; U33_L2.6@154.456,99.967 v1(155.084,99.967)
  Bottom Layer w0.254: v1(152.075,101.224) 152.075,101.165 152.676,100.564 154.488,100.564 v1(155.084,99.967)
MONITOR_S4_GaN_ISO_L3: C206_L3.2 R316_L3.1 U33_L3.6 | length 40.9
  Top Layer w0.254: R316_L3.1@203.725,73.155 203.718,73.147 v1(203.718,72.142) 204.726,72.142 207.168,69.7 230.4,69.7 231.917,71.217 234.068,71.217 v1(236.075,73.224) C206_L3.2@236.075,74.063 ; U33_L3.6@238.456,71.967 v1(239.084,71.967)
  Bottom Layer w0.254: v1(236.075,73.224) 236.075,73.165 236.676,72.564 238.488,72.564 v1(239.084,71.967)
